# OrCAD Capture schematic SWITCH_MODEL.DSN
size A
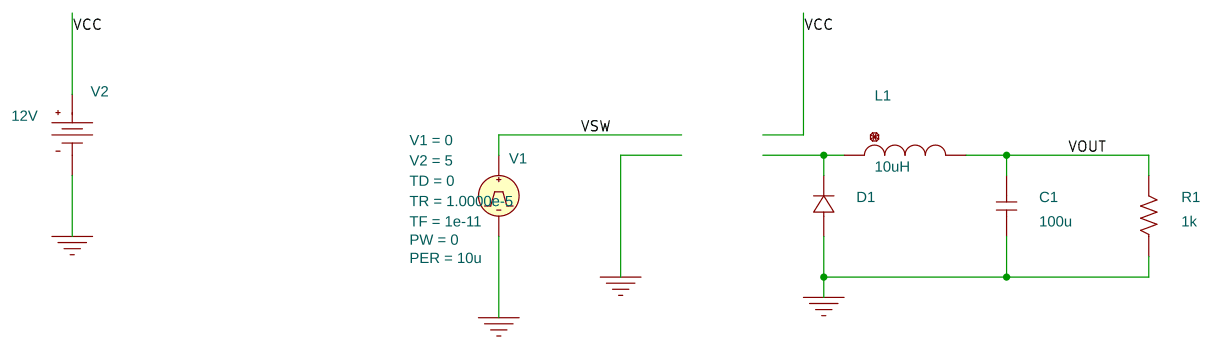
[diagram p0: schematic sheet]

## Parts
C1  100u  [cap196]
D1  Dbreak
L1  10uH  [DISC350x175LS200x100034]
R1  1k  [AXRC05]
V1  VPULSE
V2  VDC

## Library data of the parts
C1 = C
D1 = Dbreak
L1 = L
R1 = R
V1 = VPULSE: AC: 0; AppProp: Pulse$Voltage$4$-1; DC: 0; PER: 10u; PW: 0; TD: 0; TF: 1e-11; TR: 1.0000e-5; V1: 0; V2: 5
V2 = VDC: AppProp: DC$Voltage$0$-1; DC: 12V

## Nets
VCC: V2.0(+)
0: C1.1 D1.0(1) R1.1 V1.2(-) V2.1(-)
VOUT: C1.2 L1.2 R1.2
VSW: V1.1(+)
N00535: D1.1(2) L1.1
